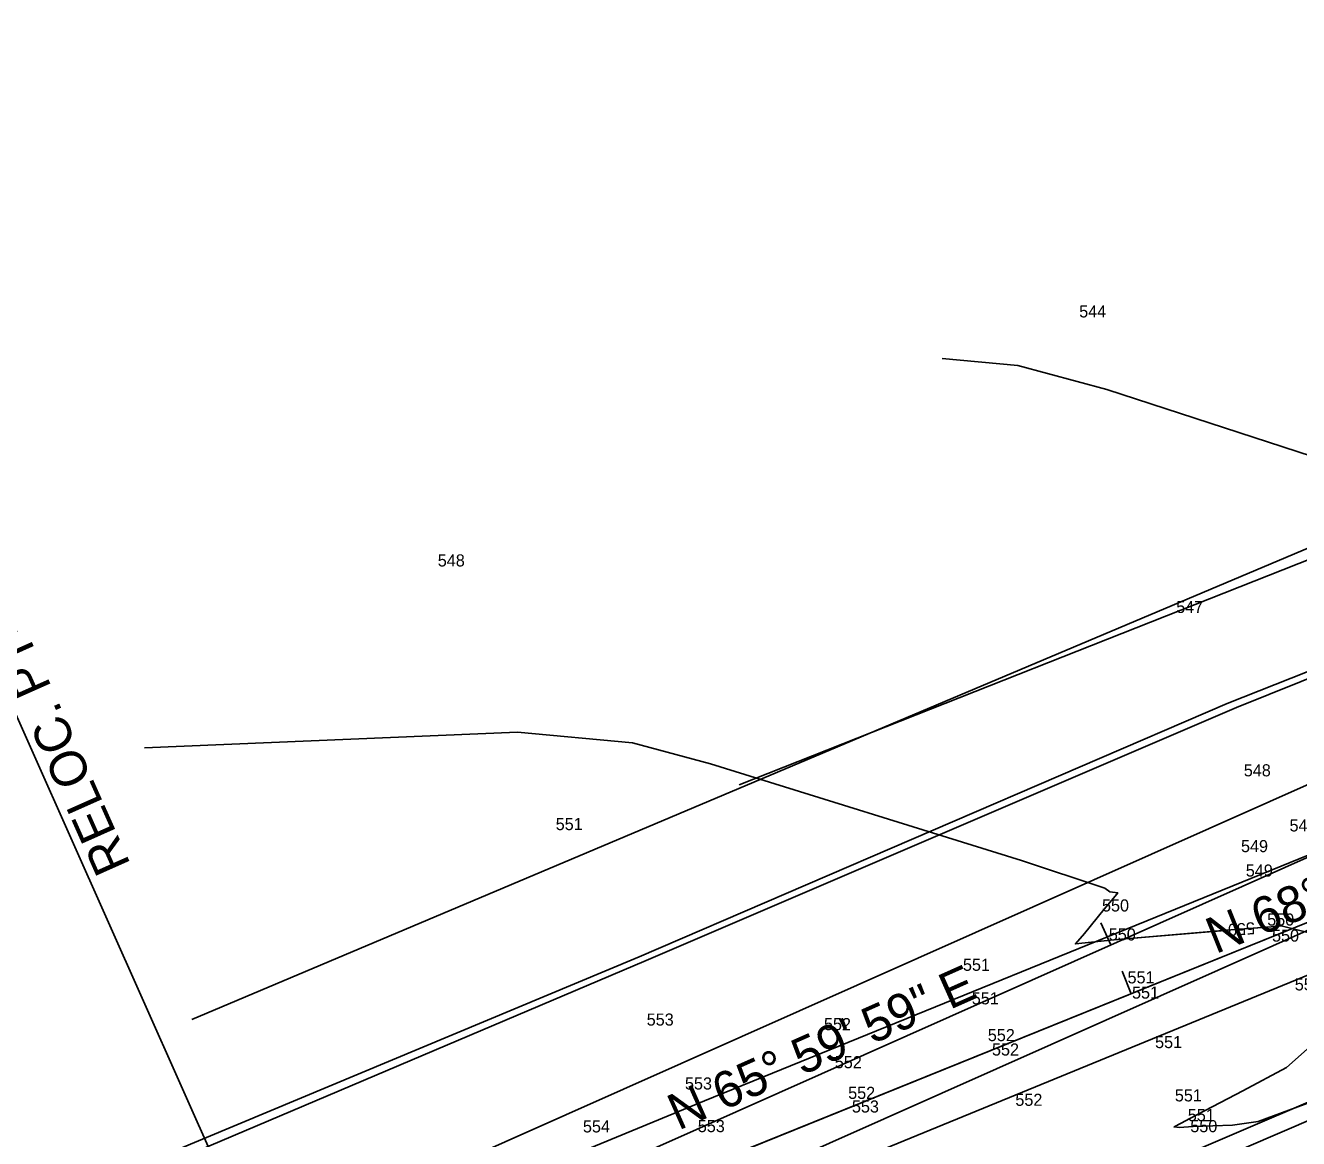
# Model space of a CAD drawing. Extents: x 1787461 to 1970323, y 938412 to 1118748.
# Drawn here: x 1966957.7 to 1967168, y 1117583.4 to 1117767.3 of the extents above; entities that cross this region are included whole.
import ezdxf

# ---------------------------------------------------------------- set-up
doc = ezdxf.new("R2010")
doc.units = 0
for name, color, linetype in [('Default', 7, 'Continuous'), ('HHA ADDITIONAL XSs', 7, 'Continuous'), ('Level 1', 7, 'Continuous'), ('RD_EX_DV_Prop', 7, 'Continuous'), ('RD_EX_Fence_Other', 7, 'Continuous'), ('RD_EX_Road', 7, 'Continuous'), ('RD_EX_VEG', 7, 'Continuous'), ('RD_HC_CL', 7, 'Continuous'), ('RD_HC_CL_Rel', 7, 'Continuous'), ('RD_HC_Data', 7, 'Continuous'), ('RD_HC_Data_Rel', 7, 'Continuous'), ('RD_HC_Data_Tic', 7, 'Continuous'), ('RD_HC_Data_Tic_Rel', 7, 'Continuous'), ('RD_PD_Final_TrvlWay', 7, 'Continuous')]:
    doc.layers.add(name, color=color, linetype=linetype)

msp = doc.modelspace()

# ---------------------------------------------------------------- linework, layer by layer
at = {"layer": 'Default'}
for points in [[(1967109.17, 1117712.29), (1967121.66, 1117711.15), (1967136.36, 1117707.16), (1967187.23, 1117690.58)], [(1967109.17, 1117712.29), (1967121.66, 1117711.15), (1967136.36, 1117707.16), (1967187.23, 1117690.58), (1967226.39, 1117682.18), (1967238.58, 1117682.48), (1967251.98, 1117680.61), (1967256.69, 1117681.12), (1967259.41, 1117681.41), (1967273.1, 1117681.06), (1967271.73, 1117678.76), (1967266.71, 1117672.16), (1967266.53, 1117671.99), (1967266.14, 1117671.61), (1967266.88, 1117671.73), (1967270.77, 1117672.26), (1967285.98, 1117674.31)], [(1967109.17, 1117712.29), (1967121.66, 1117711.15), (1967136.36, 1117707.16), (1967187.23, 1117690.58), (1967226.39, 1117682.18), (1967238.58, 1117682.48), (1967251.98, 1117680.61), (1967256.69, 1117681.12), (1967259.41, 1117681.41), (1967273.1, 1117681.06), (1967271.73, 1117678.76), (1967266.71, 1117672.16), (1967266.53, 1117671.99), (1967266.14, 1117671.61), (1967266.88, 1117671.73), (1967270.77, 1117672.26), (1967285.98, 1117674.31)], [(1967109.17, 1117712.29), (1967121.66, 1117711.15), (1967136.36, 1117707.16), (1967187.23, 1117690.58), (1967226.39, 1117682.18), (1967238.58, 1117682.48), (1967251.98, 1117680.61), (1967256.69, 1117681.12), (1967259.41, 1117681.41), (1967273.1, 1117681.06), (1967271.73, 1117678.76), (1967266.71, 1117672.16), (1967266.53, 1117671.99), (1967266.14, 1117671.61), (1967266.88, 1117671.73), (1967270.77, 1117672.26), (1967285.98, 1117674.31)], [(1967109.17, 1117712.29), (1967121.66, 1117711.15), (1967136.36, 1117707.16), (1967187.23, 1117690.58), (1967226.39, 1117682.18), (1967238.58, 1117682.48), (1967251.98, 1117680.61), (1967256.69, 1117681.12), (1967259.41, 1117681.41), (1967273.1, 1117681.06), (1967271.73, 1117678.76), (1967266.71, 1117672.16), (1967266.53, 1117671.99), (1967266.14, 1117671.61), (1967266.88, 1117671.73), (1967270.77, 1117672.26), (1967285.98, 1117674.31)], [(1967109.17, 1117712.29), (1967121.66, 1117711.15), (1967136.36, 1117707.16), (1967187.23, 1117690.58), (1967226.39, 1117682.18), (1967238.58, 1117682.48), (1967251.98, 1117680.61), (1967256.69, 1117681.12), (1967259.41, 1117681.41), (1967273.1, 1117681.06), (1967271.73, 1117678.76), (1967266.71, 1117672.16), (1967266.53, 1117671.99), (1967266.14, 1117671.61), (1967266.88, 1117671.73), (1967270.77, 1117672.26), (1967285.98, 1117674.31)], [(1967109.17, 1117712.29), (1967121.66, 1117711.15), (1967136.36, 1117707.16), (1967187.23, 1117690.58), (1967226.39, 1117682.18), (1967238.58, 1117682.48), (1967251.98, 1117680.61), (1967256.69, 1117681.12), (1967259.41, 1117681.41), (1967273.1, 1117681.06), (1967271.73, 1117678.76), (1967266.71, 1117672.16), (1967266.53, 1117671.99), (1967266.14, 1117671.61), (1967266.88, 1117671.73), (1967270.77, 1117672.26), (1967285.98, 1117674.31)], [(1966977.3, 1117647.93), (1967038.94, 1117650.5), (1967057.98, 1117648.77), (1967070.84, 1117645.27), (1967122.26, 1117629.31), (1967136.01, 1117624.71), (1967136.88, 1117624.14), (1967138.16, 1117623.99), (1967137.73, 1117623.4), (1967135.94, 1117621.25), (1967132.69, 1117617.26), (1967131.16, 1117615.51), (1967137.5, 1117616.22), (1967156.13, 1117617.77), (1967163.52, 1117618.37), (1967164.33, 1117618.43), (1967165.16, 1117618.5), (1967170.66, 1117617.16)], [(1966977.3, 1117647.93), (1967038.94, 1117650.5), (1967057.98, 1117648.77), (1967070.84, 1117645.27), (1967122.26, 1117629.31), (1967136.01, 1117624.71), (1967136.88, 1117624.14), (1967138.16, 1117623.99), (1967137.73, 1117623.4), (1967135.94, 1117621.25), (1967132.69, 1117617.26), (1967131.16, 1117615.51), (1967137.5, 1117616.22), (1967155.25, 1117617.69)], [(1966977.3, 1117647.93), (1967038.94, 1117650.5), (1967057.98, 1117648.77), (1967070.84, 1117645.27), (1967122.26, 1117629.31), (1967136.01, 1117624.71), (1967136.88, 1117624.14), (1967138.16, 1117623.99), (1967137.73, 1117623.4), (1967135.94, 1117621.25), (1967132.69, 1117617.26), (1967131.16, 1117615.51), (1967137.5, 1117616.22), (1967155.25, 1117617.69)], [(1966977.3, 1117647.93), (1967038.94, 1117650.5), (1967057.98, 1117648.77), (1967070.84, 1117645.27), (1967122.26, 1117629.31), (1967136.01, 1117624.71), (1967136.88, 1117624.14), (1967138.16, 1117623.99), (1967137.73, 1117623.4), (1967135.94, 1117621.25), (1967132.69, 1117617.26), (1967131.16, 1117615.51), (1967137.5, 1117616.22), (1967155.25, 1117617.69)], [(1966977.3, 1117647.93), (1967038.94, 1117650.5), (1967057.98, 1117648.77), (1967070.84, 1117645.27), (1967122.26, 1117629.31), (1967136.01, 1117624.71), (1967136.88, 1117624.14), (1967138.16, 1117623.99), (1967137.73, 1117623.4), (1967135.94, 1117621.25), (1967132.69, 1117617.26), (1967131.16, 1117615.51), (1967137.5, 1117616.22), (1967155.25, 1117617.69)], [(1966977.3, 1117647.93), (1967038.94, 1117650.5), (1967057.98, 1117648.77), (1967070.84, 1117645.27), (1967122.26, 1117629.31), (1967136.01, 1117624.71), (1967136.88, 1117624.14), (1967138.16, 1117623.99), (1967137.73, 1117623.4), (1967135.94, 1117621.25), (1967132.69, 1117617.26), (1967131.16, 1117615.51), (1967137.5, 1117616.22), (1967155.25, 1117617.69)], [(1966977.3, 1117647.93), (1967038.94, 1117650.5), (1967057.98, 1117648.77), (1967070.84, 1117645.27), (1967122.26, 1117629.31), (1967136.01, 1117624.71), (1967136.88, 1117624.14), (1967138.16, 1117623.99), (1967137.73, 1117623.4), (1967135.94, 1117621.25), (1967132.69, 1117617.26), (1967131.16, 1117615.51), (1967137.5, 1117616.22), (1967155.25, 1117617.69)], [(1967161.23, 1117618.18), (1967163.52, 1117618.37), (1967164.33, 1117618.43), (1967165.16, 1117618.5), (1967170.66, 1117617.16)], [(1967161.23, 1117618.18), (1967163.52, 1117618.37), (1967164.33, 1117618.43), (1967165.16, 1117618.5), (1967170.66, 1117617.16)], [(1967161.23, 1117618.18), (1967163.52, 1117618.37), (1967164.33, 1117618.43), (1967165.16, 1117618.5), (1967170.66, 1117617.16)], [(1967161.23, 1117618.18), (1967163.52, 1117618.37), (1967164.33, 1117618.43), (1967165.16, 1117618.5), (1967170.66, 1117617.16)], [(1967161.23, 1117618.18), (1967163.52, 1117618.37), (1967164.33, 1117618.43), (1967165.16, 1117618.5), (1967170.66, 1117617.16)], [(1967161.23, 1117618.18), (1967163.52, 1117618.37), (1967164.33, 1117618.43), (1967165.16, 1117618.5), (1967170.66, 1117617.16)], [(1967171.42, 1117599.91), (1967166.07, 1117595.09), (1967158.85, 1117591.25), (1967150.1, 1117586.65), (1967148.65, 1117585.89), (1967147.46, 1117585.27), (1967148.32, 1117585.18), (1967150.63, 1117585.36), (1967157.15, 1117585.54), (1967161.37, 1117586.18), (1967175.08, 1117591.23)], [(1967171.42, 1117599.91), (1967166.07, 1117595.09), (1967158.85, 1117591.25), (1967150.1, 1117586.65), (1967148.65, 1117585.89), (1967147.46, 1117585.27), (1967148.32, 1117585.18), (1967150.63, 1117585.36), (1967157.15, 1117585.54), (1967161.37, 1117586.18), (1967175.08, 1117591.23)], [(1967171.42, 1117599.91), (1967166.07, 1117595.09), (1967158.85, 1117591.25), (1967150.1, 1117586.65), (1967148.65, 1117585.89), (1967147.46, 1117585.27), (1967148.32, 1117585.18), (1967150.63, 1117585.36), (1967157.15, 1117585.54), (1967161.37, 1117586.18), (1967175.08, 1117591.23)], [(1967171.42, 1117599.91), (1967166.07, 1117595.09), (1967158.85, 1117591.25), (1967150.1, 1117586.65), (1967148.65, 1117585.89), (1967147.46, 1117585.27), (1967148.32, 1117585.18), (1967150.63, 1117585.36), (1967157.15, 1117585.54), (1967161.37, 1117586.18), (1967175.08, 1117591.23)], [(1967171.42, 1117599.91), (1967166.07, 1117595.09), (1967158.85, 1117591.25), (1967150.1, 1117586.65), (1967148.65, 1117585.89), (1967147.46, 1117585.27), (1967148.32, 1117585.18), (1967150.63, 1117585.36), (1967157.15, 1117585.54), (1967161.37, 1117586.18), (1967175.08, 1117591.23)], [(1967171.42, 1117599.91), (1967166.07, 1117595.09), (1967158.85, 1117591.25), (1967150.1, 1117586.65), (1967148.65, 1117585.89), (1967147.46, 1117585.27), (1967148.32, 1117585.18), (1967150.63, 1117585.36), (1967157.15, 1117585.54), (1967161.37, 1117586.18), (1967175.08, 1117591.23)], [(1967171.42, 1117599.91), (1967166.07, 1117595.09), (1967158.85, 1117591.25), (1967150.1, 1117586.65), (1967148.65, 1117585.89), (1967147.46, 1117585.27), (1967148.32, 1117585.18), (1967150.63, 1117585.36), (1967157.15, 1117585.54), (1967161.37, 1117586.18), (1967175.08, 1117591.23)]]:
    msp.add_lwpolyline(points, dxfattribs=at)
at = {"layer": 'HHA ADDITIONAL XSs'}
msp.add_lwpolyline([(1969266.55, 1117963.61), (1967907.56, 1117966.55), (1967403.98, 1117771.66), (1967075.57, 1117641.84)], dxfattribs=at)
at = {"layer": 'Level 1'}
msp.add_lwpolyline([(1968647.29, 1117975.82), (1967967.92, 1117975.82), (1967727.47, 1117916.63), (1966985.13, 1117603.01)], dxfattribs=at)
at = {"layer": 'RD_EX_DV_Prop'}
msp.add_line((1966769.51, 1117457.48), (1967696.84, 1117832.06), dxfattribs=at)
at = {"layer": 'RD_EX_Fence_Other'}
for points in [[(1966803.22, 1117549.06), (1966808.8, 1117506.9), (1966864.07, 1117525.43), (1966962.8, 1117571.4), (1967060.23, 1117612.78), (1967157.77, 1117654.58), (1967254.5, 1117693.48), (1967317.6, 1117718.63)], [(1966879.09, 1117474.94), (1966985.88, 1117513.17), (1967082.44, 1117548.84), (1967188.89, 1117594.6), (1967260.47, 1117628.39)]]:
    msp.add_lwpolyline(points, dxfattribs=at)
at = {"layer": 'RD_EX_Road'}
for points in [[(1966768.28, 1117466.83), (1966868.93, 1117506.7), (1966969.96, 1117548.31), (1967069.86, 1117589.6), (1967171.37, 1117630.89), (1967269.56, 1117671.02), (1967319.89, 1117691.93), (1967370.29, 1117712.23), (1967469.03, 1117750.91), (1967565.44, 1117788.86), (1967660.02, 1117826.88), (1967693.17, 1117840.55), (1967696.66, 1117832.16)], [(1966774.52, 1117449.93), (1966874.96, 1117489.75), (1966977.23, 1117531.51), (1967077.03, 1117572.42), (1967179.47, 1117614.42), (1967276.75, 1117654.08), (1967307.6, 1117666.03)]]:
    msp.add_lwpolyline(points, dxfattribs=at)
at = {"layer": 'RD_EX_VEG'}
for points in [[(1966803.22, 1117549.06), (1966801.85, 1117502.56), (1966864.07, 1117525.43), (1966961.82, 1117572.79), (1967059.09, 1117613.38), (1967156.27, 1117655.27), (1967254.08, 1117694.01), (1967316.99, 1117719.5)], [(1966832.92, 1117460.39), (1966879.09, 1117474.94), (1966985, 1117515.6), (1967082.35, 1117552.01), (1967187.28, 1117596.9), (1967283.89, 1117634.57), (1967305.16, 1117647.66)]]:
    msp.add_lwpolyline(points, dxfattribs=at)
at = {"layer": 'RD_HC_CL'}
msp.add_line((1966769.51, 1117457.48), (1967848.24, 1117893.22), dxfattribs=at)
at = {"layer": 'RD_HC_CL_Rel'}
msp.add_line((1967000.16, 1117554.42), (1967182.71, 1117635.7), dxfattribs=at)
at = {"layer": 'RD_HC_Data_Rel'}
msp.add_line((1967000.16, 1117554.42), (1966940.2, 1117689.08), dxfattribs=at)
at = {"layer": 'RD_HC_Data_Tic'}
msp.add_line((1967140.4, 1117607.29), (1967138.9, 1117611), dxfattribs=at)
at = {"layer": 'RD_HC_Data_Tic_Rel'}
msp.add_line((1967137, 1117615.35), (1967135.37, 1117619), dxfattribs=at)
at = {"layer": 'RD_PD_Final_TrvlWay'}
for p, q in [((1966995.68, 1117564.47), (1967178.24, 1117645.75)), ((1967004.63, 1117544.37), (1967187.19, 1117625.65))]:
    msp.add_line(p, q, dxfattribs=at)

# ---------------------------------------------------------------- texts
at = {"layer": 'Default'}
for s, p in [('544', (1967131.79, 1117719.07)), ('548', (1967025.79, 1117677.91)), ('547', (1967147.82, 1117670.22)), ('548', (1967158.99, 1117643.22)), ('551', (1967045.28, 1117634.33)), ('549', (1967166.55, 1117634.11)), ('549', (1967158.53, 1117630.69)), ('549', (1967159.32, 1117626.65)), ('550', (1967135.56, 1117620.88)), ('550', (1967162.86, 1117618.55)), ('550', (1967136.68, 1117616.09)), ('550', (1967163.66, 1117615.9)), ('551', (1967112.58, 1117611.07)), ('551', (1967139.78, 1117609)), ('550', (1967167.42, 1117607.83)), ('551', (1967114.04, 1117605.53)), ('551', (1967140.52, 1117606.48)), ('553', (1967060.32, 1117602.02)), ('552', (1967089.61, 1117601.26)), ('552', (1967116.69, 1117599.45)), ('551', (1967144.33, 1117598.3)), ('552', (1967117.38, 1117597.07)), ('552', (1967091.4, 1117594.97)), ('553', (1967066.64, 1117591.45)), ('552', (1967093.61, 1117589.9)), ('552', (1967121.24, 1117588.76)), ('551', (1967147.6, 1117589.49)), ('553', (1967094.23, 1117587.65)), ('551', (1967149.74, 1117586.22)), ('554', (1967049.78, 1117584.36)), ('553', (1967068.76, 1117584.41)), ('550', (1967150.15, 1117584.4))]:
    msp.add_text(s, height=2, dxfattribs=at).set_placement(p)
msp.add_text('550', height=2, rotation=184.6743, dxfattribs=at).set_placement((1967160.76, 1117619.15))
msp.add_text('550', height=2, rotation=184.6743, dxfattribs=at).set_placement((1967160.76, 1117619.15))
msp.add_text('550', height=2, rotation=184.6743, dxfattribs=at).set_placement((1967160.76, 1117619.15))
msp.add_text('550', height=2, rotation=184.6743, dxfattribs=at).set_placement((1967160.76, 1117619.15))
msp.add_text('550', height=2, rotation=184.6743, dxfattribs=at).set_placement((1967160.76, 1117619.15))
msp.add_text('550', height=2, rotation=184.6743, dxfattribs=at).set_placement((1967160.76, 1117619.15))
at = {"layer": 'RD_HC_Data'}
msp.add_text('N 68%%d 00\' 15" E', height=6, rotation=21.9958, dxfattribs=at).set_placement((1967154.33, 1117613.81))
at = {"layer": 'RD_HC_Data_Rel'}
for s, rotation, p in [('RELOC. PT=52+50.21', 114.0002, (1966975.09, 1117628.64)), ('N 65%%d 59\' 59" E', 24.0002, (1967065.56, 1117584.64))]:
    msp.add_text(s, height=6, rotation=rotation, dxfattribs=at).set_placement(p)

doc.saveas('drawing.dxf')
